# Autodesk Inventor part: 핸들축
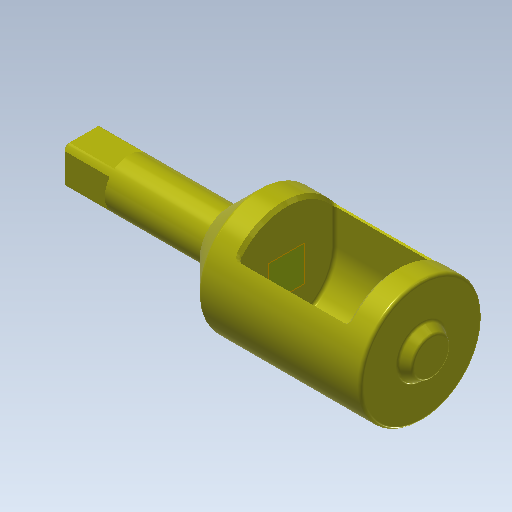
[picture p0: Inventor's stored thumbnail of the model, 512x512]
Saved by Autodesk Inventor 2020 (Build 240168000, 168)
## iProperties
Created: 2018-01
Part Number: 핸들축
Material: 강철, 연강
Document SubType Name: Modeling
Designer: mduedu
Density: 1 g/cm^3
Appearance: 노란색
Author: mduedu
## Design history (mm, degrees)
sketch "스케치1"
  geometry: L1 (0, 0)-(-109, 0); L2 (-46, -7.5)-(0, -7.5); L3 (0, -7.5)-(0, 0); L4 (-106, -19)-(-46, -19); L5 (-46, -19)-(-46, -7.5); L6 (-106, -7.5)-(-106, -19); L7 (-109, -5.768)-(-106, -7.5); L8 (-109, -5.768)-(-109, 0)
  constraints: 16 end point, 2 parallel, 1 horizontal, 1 vertical
  dimensions: "d8" = 15 diameter of L2 L1; "d43" = 46 distance between parallel lines of L3 L5; "d47" = 60 distance between parallel lines of L5 L6; "d63" = 3 distance between parallel lines of L6 L8; "d77" = 38 diameter of L4 L1; "d78" = 15 diameter of L6.start L1; "d79" = 30 deg angle of L1 L7
revolve "회전1" sketch "스케치1" stored, may be unused: angle "d9" = 90 deg
sketch "스케치4"
  geometry: L1 (-6, -6)-(-4.5, -6); L2 (6, -6)-(6, -4.5); L3 (6, 6)-(4.5, 6); L4 (-6, 6)-(-6, 4.5); L5 (-6, -6)-(6, 6); L6 (6, -6)-(-6, 6); L7 (-4.5, 6)-(-6, 6); L8 (-6, 4.5)-(-6, -4.5); L9 (-6, -4.5)-(-6, -6); L10 (-4.5, -6)-(4.5, -6); L11 (4.5, -6)-(6, -6); L12 (6, -4.5)-(6, 4.5); L13 (6, 4.5)-(6, 6); L14 (4.5, 6)-(-4.5, 6); C1 r 7.5 at (0, 0) reference; 2 further points
  constraints: 28 end point, 18 parallel, 9 perpendicular, 3 horizontal, 2 midpoint, 1 coincident, 11 other
  dimensions: "d20" = 12 distance of L4.start L3.start; "d21" = 12 distance of L3.start L2.start (= d20)
extrude "돌출2" cut sketch "스케치4" distance "d22" = 15; taper "d23" = 0 deg
chamfer "모따기2" distance "d24" = 1; stored, may be unused: second distance "d25" = 2, angle "d26" = 45 deg
sketch "스케치5"
  geometry: 2 further points
  constraints: 1 coincident
hole "구멍1" sketch "스케치5" at (5, 4.153) diameter "d27" = 2.459; stored, may be unused: countersink angle "d31" = 90 deg, drill point angle "d33" = 120 deg; dims "d28" = 6.9, "d29" = 4, "d30" = 2, "d32" = 8.4
node "작업 평면1"
sketch "스케치9"
  geometry: L1 (10, 4.153)-(10, 15.815); L2 (-20, 4.153)-(-20, 15.815); A1 r 15 centre (-5, 4.153) between (-20, 4.153) and (10, 4.153); A2 r 19 centre (-5, 4.153) between (10, 15.815) and (-20, 15.815) reference; 1 further point
  constraints: 4 end point, 4 point on circle, 2 tangent, 1 centre point, 1 coincident, 1 concentric, 1 parallel, 1 vertical
  dimensions: "d76" = 4 radial gap between concentric circles of A2 A1
extrude "돌출4" cut sketch "스케치9" distance "d73" = 34; taper "d74" = 0 deg
chamfer "모따기3" distance "d44" = 10; stored, may be unused: second distance "d45" = 2, angle "d46" = 45 deg
fillet "모깎기4" dims "d80" = 1
chamfer "모따기5" distance "d81" = 1; stored, may be unused: second distance "d82" = 2, angle "d83" = 45 deg
node "솔리드1"
other parameters: "d75" = -64
